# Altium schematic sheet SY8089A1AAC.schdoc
size 127 x 101 mm
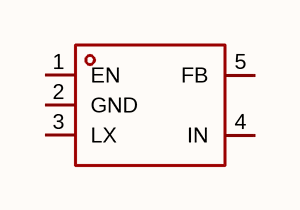
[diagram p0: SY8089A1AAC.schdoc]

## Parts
U?  sy8089a1aac  [TSOT-23-5_L2.9-W1.6-P0.95-LS2.8-BR]  (value not drawn)

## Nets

Not connected (* = marked no-connect by the designer): U? 1(EN) 2(GND) 3(LX) 4(IN) 5(FB)

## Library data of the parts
U? = sy8089a1aac: 功能类型:降压型;工作电压:2.5V~5.5V;输出电压:-;输出电流:2A;输出类型:可调;; Manufacturer: Silergy(矽力杰); AddInBom: yes; ModelId: b5108020abe84f7bb0f3c398b43b6e0b; ModelName: TSOT-23-5_L2.9-W1.6-H1.00-LS2.8-P0.95; ModelTransform: 110.45568,114.173,0,180,0,0,0,0,0; Function: 降压型; Output Current: 2A; Frequency - Switching: 1.5MHz; Synchronous Rectifier: 是; Number of Outputs: 1; Topology: 降压式; Quiescent Current: 50uA; Switch tube (built-in/external): 内置; Output Type: 可调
